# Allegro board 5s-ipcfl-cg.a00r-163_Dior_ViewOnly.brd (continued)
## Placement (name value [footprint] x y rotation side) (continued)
Q940  NX7002AK  [TX_SOT23_2D4_T01_H43]  54.74 48.76 180 bottom
Q941  NX7002AK  [TX_SOT23_2D4_T01_H43]  28.88 34.48 90 bottom
Q942  NX7002AK  [TX_SOT23_2D4_T01_H43]  33.5 34.91 90 bottom
Q4000  PJ2301  [TX_SOT23_2D4_122X55_H43]  23.34 136.15 90 top
Q4001  LMBT3904LT1G  [TX_SOT23_2D4_122X55_H44]  24.23 143.55 270 bottom
Q7201  NX7002AK  [TX_SOT23_2D4_T01_H43]  6.53 70.65 180 bottom
Q9308  NX7002AK  [TX_SOT23_2D4_T01_H43]  165.05 39.04 90 bottom
Q9309  NX7002AK  [TX_SOT23_2D4_T01_H43]  165.23 42.4 90 bottom
Q9344  LMBT3904LT1G  [TX_SOT23_2D4_122X55_H44]  163.98 24.84 0 top
Q9345  LMBT3904LT1G  [TX_SOT23_2D4_122X55_H44]  165.06 35.53 90 bottom
Q9346  LMBT3904LT1G  [TX_SOT23_2D4_122X55_H44]  166.96 38.53 270 top
Q9432  SSM6N15FU  [TX_SOIC_6P_26_87X53_COLY]  143.99 158.99 180 top
Q9433  AO3404A  [MX_SOT23_2D4_122X71]  6.68 127.62 180 bottom
Q9434  NX7002AK  [TX_SOT23_2D4_T01_H43]  30.12 59.17 270 top
Q9435  NX7002AK  [TX_SOT23_2D4_T01_H43]  29.09 51.48 180 top
Q9436  NX7002AK  [TX_SOT23_2D4_T01_H43]  31.24 31.1 90 bottom
Q9437  NX7002AK  [TX_SOT23_2D4_T01_H43]  32.43 27.8 270 bottom
Q9438  LMBT3904LT1G  [TX_SOT23_2D4_122X55_H44]  29.44 35.65 90 top
Q9534  NX7002AK  [TX_SOT23_2D4_T01_H43]  29.69 29.58 270 top
Q9535  NX7002AK  [TX_SOT23_2D4_T01_H43]  29.69 26.28 270 top
Q9537  NX7002AK  [TX_SOT23_2D4_T01_H43]  121.49 34.73 270 bottom
Q9540  NX7002AK  [TX_SOT23_2D4_T01_H43]  126.52 31.4 90 bottom
Q9541  NX7002AK  [TX_SOT23_2D4_T01_H43]  121.65 24.61 180 bottom
Q9542  NX7002AK  [TX_SOT23_2D4_T01_H43]  126.52 28.12 90 bottom
Q9543  NX7002AK  [TX_SOT23_2D4_T01_H43]  125 40.09 0 bottom
Q9544  NX7002AK  [TX_SOT23_2D4_T01_H43]  130.82 38.66 0 bottom
Q93025  AO3404A  [MX_SOT23_2D4_122X71]  154.28 169.03 180 top
Q93033  RN47A4  [MX_SOT323_S5]  133.15 169.03 0 top
Q93034  SIA432DJ-T4-GE3  [MX_SC70_6_VISHAY_T01]  110.85 38.36 180 bottom
Q93035  LMBT3904LT1G  [TX_SOT23_2D4_122X55_H44]  114.33 37.74 0 bottom
Q93036  LMBT3904LT1G  [TX_SOT23_2D4_122X55_H44]  163.98 29.46 0 top
Q93037  NX7002AK  [TX_SOT23_2D4_T01_H43]  121.54 28.11 270 bottom
Q93038  NX7002AK  [TX_SOT23_2D4_T01_H43]  121.52 31.46 270 bottom
Q93041  AO3404A  [MX_SOT23_2D4_122X71]  104.11 164.07 180 top
R1  330 OHM  [MX_R0402_SMALL_T01]  37.34 162.63 270 top
R2  330 OHM  [MX_R0402_SMALL_T01]  36.07 162.63 270 top
R3  0Ohm  [MX_R0402_SHORT_SMALL_T01]  79.57 76.51 180 top
R4  0Ohm  [MX_R0402_SHORT_SMALL_T01]  83.65 75.7 180 top
R5  0Ohm  [MX_R0402_SHORT_SMALL_T01]  82.02 75.25 180 top
R6  0Ohm  [MX_R0402_SHORT_SMALL_T01]  118.6 24 270 bottom
R19  0Ohm  [MX_R0805_SMALL_T02]  4.42 158.94 90 top
R20  0Ohm  [MX_R0805_SMALL_T02]  6.2 158.94 90 top
R21  0Ohm  [MX_R0805_SMALL_T02]  10.39 158.94 90 top
R22  0Ohm  [MX_R0805_SMALL_T02]  12.17 158.94 90 top
R23  75  [MX_R0805_SMALL_T02]  6.81 161.97 270 bottom
R36  2.2KOHM  [MX_R0402_SMALL_T01]  34.85 15.53 0 top
R37  2.2KOHM  [MX_R0402_SMALL_T01]  35.25 17.11 180 top
R38  2.2KOHM  [MX_R0402_SMALL_T01]  61.26 71.52 0 bottom
R39  2.2K  [MX_R0402_SMALL_T01]  43.14 105.34 90 bottom
R40  2.2K  [MX_R0402_SMALL_T01]  41.43 108.63 270 top
R55  390 Ohm  [MX_R0603_SMALL_T01]  2.24 26.17 180 top
R56  10KOhm  [MX_R0402_SMALL_T01]  4.8 30.34 90 top
R59  510 Ohm  [MX_R0603_SMALL_T01]  28.57 76.34 270 top
R60  10KOhm  [MX_R0402_SMALL_T01]  29.01 98.41 180 bottom
R62  4.7KOHM  [MX_R0402_SMALL_T01]  160.73 65.62 270 bottom
R70  1KOhm  [MX_R0402_SMALL_T01]  25.91 149.44 90 top
R71  20KOhm  [MX_R0402_SMALL_T01]  19.94 148.71 180 top
R79  4.7K  [MX_R0402_SMALL_T01]  48.94 140.73 180 top
R80  20KOhm  [MX_R0402_SMALL_T01]  19.94 147.74 180 top
R113  1K  [MX_R0402_SMALL_T01]  21.19 23.49 180 bottom
R123  22K  [MX_R0402_SMALL_T01]  40.19 15.01 270 top
R124  22K  [MX_R0402_SMALL_T01]  43.23 15.61 180 top
R181  0  [MX_R0402_SMALL_T01]  24.29 29.97 270 bottom
R182  0  [MX_R0402_SMALL_T01]  7.31 18.79 0 top
R203  3.3Ohm  [MX_R0402_SMALL_T01]  166.85 48.43 0 bottom
R204  3.3Ohm  [MX_R0402_SMALL_T01]  165.05 48.43 180 bottom
R205  100  [MX_R0402_SMALL_T01]  83.79 155.69 270 top
R206  0Ohm  [MX_R0402_SHORT_SMALL_T01]  82.52 155.69 270 top
R207  100  [MX_R0402_SMALL_T01]  6.7 37.33 90 top
R637  22  [MX_R0402_SMALL_T01]  32.23 87.09 180 bottom
R651  330 Ohm  [MX_R0603_SMALL_T01]  118.91 34.62 270 bottom
R658  330 Ohm  [MX_R0603_SMALL_T01]  129.73 28.11 180 bottom
R661  330 Ohm  [MX_R0603_SMALL_T01]  121.9 40.16 270 bottom
R663  1KOhm  [MX_R0402_SMALL_T01]  127.14 40.94 90 bottom
R931  1KOhm  [MX_R0402_SMALL_T01]  56.51 46.14 0 bottom
R932  330 Ohm  [MX_R0603_SMALL_T01]  57.53 49.34 180 bottom
R933  1KOhm  [MX_R0402_SMALL_T01]  33.63 32.55 90 bottom
R934  330 Ohm  [MX_R0603_SMALL_T01]  33.12 37.66 270 bottom
R2101  10K  [MX_R0402_SMALL_T01]  64.74 108.32 180 top
R2102  100K  [MX_R0402_SMALL_T01]  61.85 108.39 270 bottom
R2103  1K  [MX_R0402_SMALL_T01]  62.89 108.4 90 top
R2104  1K  [MX_R0402_SMALL_T01]  61.06 108.39 90 top
R2341  10K  [MX_R0402_SMALL_T01]  35.76 98.8 0 bottom
R2342  10K  [MX_R0402_SMALL_T01]  19.53 133.09 0 top
R2343  10K  [MX_R0402_SMALL_T01]  34.31 99.13 90 bottom
R2344  10K  [MX_R0402_SMALL_T01]  33.63 105.96 180 top
R2345  10K  [MX_R0402_SMALL_T01]  33.4 107.91 0 bottom
R2346  10K  [MX_R0402_SMALL_T01]  22.12 116.19 0 bottom
R2347  10K  [MX_R0402_SMALL_T01]  33.5 107.79 180 top
R2348  10K  [MX_R0402_SMALL_T01]  31.52 106.48 0 top
R2349  10K  [MX_R0402_SMALL_T01]  30.25 108.54 270 bottom
R2350  10K  [MX_R0402_SMALL_T01]  33.44 106.9 0 bottom
R2351  10K  [MX_R0402_SMALL_T01]  31.79 107.94 90 top
R2352  10K  [MX_R0402_SMALL_T01]  33.5 106.87 180 top
R2353  1M  [MX_R0402_SMALL_T01]  44.19 103.59 270 bottom
R2354  10K  [MX_R0402_SMALL_T01]  43.28 103.61 270 bottom
R2420  30  [MX_R0402_SMALL_T01]  50.24 103.93 0 bottom
R3106  0Ohm  [MX_R0402_SHORT_SMALL_T01]  60.63 20.94 270 bottom
R3107  0Ohm  [MX_R0402_SHORT_SMALL_T01]  39.62 58.66 180 bottom
R3108  0  [MX_R0402_SMALL_T01]  59.03 53.08 90 bottom
R3109  0  [MX_R0402_SMALL_T01]  59.14 55.06 180 top
R3110  10K  [MX_R0402_SMALL_T01]  52.91 102.45 180 bottom
R3111  0Ohm  [MX_R0402_SHORT_SMALL_T01]  27.56 88.04 180 top
R3112  0Ohm  [MX_R0402_SHORT_SMALL_T01]  53.74 101.22 180 bottom
R3113  0Ohm  [MX_R0402_SHORT_SMALL_T01]  36.5 57.6 90 bottom
R3114  0Ohm  [MX_R0402_SHORT_SMALL_T01]  37.41 57.6 90 bottom
R3115  0Ohm  [MX_R0402_SHORT_SMALL_T01]  38.68 56.87 270 bottom
R3116  0Ohm  [MX_R0402_SHORT_SMALL_T01]  39.62 56.85 270 bottom
R3117  0Ohm  [MX_R0402_SHORT_SMALL_T01]  40.92 57.77 90 bottom
R3118  0Ohm  [MX_R0402_SHORT_SMALL_T01]  41.83 57.8 90 bottom
R3119  0Ohm  [MX_R0402_SHORT_SMALL_T01]  44.78 57.47 180 bottom
R3120  0Ohm  [MX_R0402_SHORT_SMALL_T01]  44.78 56.56 180 bottom
R3121  0Ohm  [MX_R0402_SHORT_SMALL_T01]  54.89 60.42 90 bottom
R3122  0Ohm  [MX_R0402_SHORT_SMALL_T01]  53.97 60.42 90 bottom
R3123  0Ohm  [MX_R0402_SHORT_SMALL_T01]  56.26 61.23 90 bottom
R3124  0Ohm  [MX_R0402_SHORT_SMALL_T01]  57.17 61.23 90 bottom
R3125  22  [MX_R0402_SMALL_T01]  38.71 47.92 270 top
R3126  33  [MX_R0402_SMALL_T01]  38.2 108.78 90 top
R3127  22  [MX_R0402_SMALL_T01]  41.38 47.77 90 top
R3128  33  [MX_R0402_SMALL_T01]  41.86 103.72 90 bottom
R3129  0Ohm  [MX_R0402_SHORT_SMALL_T01]  46.39 47.77 90 top
R3130  0Ohm  [MX_R0402_SHORT_SMALL_T01]  47.75 44.11 180 top
R3131  0Ohm  [MX_R0402_SHORT_SMALL_T01]  47.46 47.53 90 top
R3132  33  [MX_R0402_SMALL_T01]  43.13 94.31 90 bottom
R3133  33  [MX_R0402_SMALL_T01]  32.46 99.15 0 top
R3134  33  [MX_R0402_SMALL_T01]  43.38 97.25 0 bottom
R3135  33  [MX_R0402_SMALL_T01]  32.5 97.48 0 bottom
R3136  1K  [MX_R0402_SMALL_T01]  53.39 52.03 90 bottom
R3138  1K  [MX_R0402_SMALL_T01]  20.9 106.29 180 top
R3139  0Ohm  [MX_R0402_SHORT_SMALL_T01]  50.87 55.39 0 bottom
R4000  0Ohm  [MX_R0805_SMALL_T02]  23.6 139.56 270 top
R4001  1K  [MX_R0402_SMALL_T01]  20.09 144.41 270 bottom
R4002  15KOhm  [MX_R0402_SMALL_T01]  19.82 142.79 270 bottom
R4003  200KOHM  [MX_R0402_SMALL_T01]  25.8 135.12 270 top
R4004  1KOhm  [MX_R0402_SMALL_T01]  21.06 142.79 90 bottom
R4005  1KOhm  [MX_R0402_SMALL_T01]  25.75 141.38 0 bottom
R4006  10KOhm  [MX_R0402_SMALL_T01]  26.17 133.85 0 top
R4007  0  [MX_R0402_SHORT_SMALL_T01]  21.06 144.41 90 bottom
R4008  0  [MX_R0402_SHORT_SMALL_T01]  24.74 138.17 270 bottom
R4009  10K  [MX_R0402_SMALL_T01]  15.09 138.8 90 bottom
R4010  2.49KOHM  [MX_R0402_SMALL_T01]  22.58 136.39 270 bottom
R4011  0Ohm  [MX_R0402_SHORT_SMALL_T01]  15.06 140.42 270 bottom
R4814  200  [MX_R0805_SMALL_T02]  161.4 25.4 270 top
R4815  200  [MX_R0805_SMALL_T02]  168 35.81 90 bottom
R4816  200  [MX_R0805_SMALL_T02]  164.7 34.46 90 top
R4817  200  [MX_R0805_SMALL_T02]  167.5 35.94 180 top
R4818  200  [MX_R0805_SMALL_T02]  168 41.65 270 top
R4820  200  [MX_R0805_SMALL_T02]  168 39.11 90 bottom
R4821  200  [MX_R0805_SMALL_T02]  167.99 44.44 90 top
R6501  10K  [MX_R0402_SMALL_T01]  30.68 33.14 90 top
R6502  1K  [MX_R0402_SMALL_T01]  31.88 30.7 0 top
R7202  8.2K  [MX_R0402_SMALL_T01]  7.34 67.05 270 top
R7203  0 Ohm  [MX_R0402_SMALL_T01]  8.23 71.74 90 top
R7204  33  [MX_R0402_SMALL_T01]  17.19 69.79 0 bottom
R7205  33  [MX_R0402_SMALL_T01]  13.77 71.82 90 bottom
R7206  33  [MX_R0402_SMALL_T01]  11.86 71.82 90 bottom
R7209  8.2K  [MX_R0402_SMALL_T01]  9.17 71.74 90 top
R7210  10K  [MX_R0402_SMALL_T01]  12.8 71.49 270 top
R7211  10K  [MX_R0402_SMALL_T01]  17.17 71.06 270 bottom
R7212  0  [MX_R0402_SMALL_T01]  9.4 67.58 0 bottom
R7213  0  [MX_R0402_SMALL_T01]  17.7 65.58 180 bottom
R7215  0  [MX_R0402_SMALL_T01]  14.2 73.14 0 top
R7216  0  [MX_R0402_SMALL_T01]  14.71 71.47 90 top
R7217  0  [MX_R0402_SMALL_T01]  7.31 64.48 270 bottom
R7218  0  [MX_R0402_SMALL_T01]  6.37 64.48 270 bottom
R7219  0Ohm  [MX_R0402_SHORT_SMALL_T01]  6.93 70.68 180 top
R8828  4.7K  [MX_R0402_SMALL_T01]  161.4 23.11 270 top
R8829  4.7K  [MX_R0402_SMALL_T01]  164.69 32.12 180 top
R60757  0Ohm  [MX_R0805_SMALL_T02]  67.79 90.03 180 top
R60758  0Ohm  [MX_R0805_SMALL_T02]  67.77 86.48 180 top
R60759  0Ohm  [MX_R0805_SMALL_T02]  69.24 91.81 180 top
R60760  0Ohm  [MX_R0805_SMALL_T02]  67.77 88.25 180 top
R60761  0Ohm  [MX_R0805_SHORT_SMALL_T02]  67.92 84.7 180 top
R69683  330 Ohm  [MX_R0603_SMALL_T01]  129.35 31.54 270 bottom
R69684  330 Ohm  [MX_R0603_SMALL_T01]  125.16 24.81 180 bottom
R69692  200K  [MX_R0402_SMALL_T01]  9.2 23.62 0 top
R69693  0Ohm  [MX_R0402_SHORT_SMALL_T01]  7.6 21.69 0 top
R69695  1K  [MX_R0402_SMALL_T01]  11.17 13.27 0 top
R69867  160OHM  [MX_R0402_SMALL_T01]  6.75 118.01 180 bottom
R70259  4.7K  [MX_R0402_SMALL_T01]  63.85 149.34 180 bottom
R70261  4.7K  [MX_R0402_SMALL_T01]  40.38 170.17 270 top
R70262  100K  [MX_R0402_SMALL_T01]  9.2 22.6 0 top
R70263  100K  [MX_R0402_SMALL_T01]  7.6 23.62 180 top
R70264  100K  [MX_R0402_SMALL_T01]  7.6 22.6 180 top
R70273  100K  [MX_R0402_SMALL_T01]  16.64 18.25 0 bottom
R70274  1KOhm  [MX_R0402_SMALL_T01]  9.45 15.83 90 top
R70275  1KOhm  [MX_R0402_SMALL_T01]  21.95 14.98 0 top
R70279  2.7K  [MX_R0402_SMALL_T01]  5.88 87.57 90 top
R70280  2.7K  [MX_R0402_SMALL_T01]  7.11 87.54 90 top
R70290  8.2KOHM  [MX_R0402_SMALL_T01]  28.9 55.67 180 top
R70291  8.2KOHM  [MX_R0402_SMALL_T01]  29.21 54.4 270 top
R70292  8.2KOHM  [MX_R0402_SMALL_T01]  32.59 28.95 270 top
R70293  8.2KOHM  [MX_R0402_SMALL_T01]  29.46 28.39 270 bottom
R70294  22K  [MX_R0402_SMALL_T01]  10.75 97.26 180 top
R70295  4.7K  [MX_R0402_SMALL_T01]  31.6 33.14 90 top
R70296  0Ohm  [MX_R0402_SHORT_SMALL_T01]  32.89 34.61 180 top
R70297  10K  [MX_R0402_SMALL_T01]  27.91 33.14 90 top
R70298  0Ohm  [MX_R0402_SHORT_SMALL_T01]  28.83 33.14 270 top
R70299  10K  [MX_R0402_SMALL_T01]  31.09 24.12 180 top
R70300  6.04KOhm  [TX_R0402]  84.05 74.03 270 top
R70301  4.7K  [MX_R0402_SMALL_T01]  93.84 28.11 270 bottom
R93098  0Ohm  [MX_R0402_SHORT_SMALL_T01]  134.29 165.98 90 top
R93100  22K  [MX_R0402_SMALL_T01]  157.2 169.53 0 top
R93101  10KOhm  [MX_R0402_SMALL_T01]  135.1 170.17 270 top
R93102  0Ohm  [MX_R0402_SHORT_SMALL_T01]  132.94 165.47 0 top
R93103  0  [MX_R0402_SMALL_T01]  110.31 40.51 180 bottom
R93104  100KOHM  [MX_R0402_SMALL_T01]  113.5 40.36 0 bottom
R93105  15KOhm  [MX_R0402_SMALL_T01]  114.34 41.32 180 bottom
R93106  10KOhm  [MX_R0402_SMALL_T01]  117.99 37.87 180 bottom
R93107  10KOhm  [MX_R0402_SMALL_T01]  116.57 36.27 90 bottom
R93108  8.2KOHM  [MX_R0402_SMALL_T01]  116.57 38.35 90 bottom
R93109  33 OHM  [MX_R0402_SMALL_T01]  108.95 43.25 180 bottom
R93110  1.5K  [MX_R0402_SMALL_T01]  108.39 41.32 0 bottom
R93111  200  [MX_R0805_SMALL_T02]  161.4 30.1 90 top
R93112  4.7K  [MX_R0402_SMALL_T01]  161.4 27.81 270 top
R93115  16KOHM  [MX_R0402_SMALL_T01]  38.48 109.03 0 bottom
R93116  59KOHM  [MX_R0402_SMALL_T01]  37.77 112.92 90 bottom
R93117  3KOHM  [MX_R0402_SMALL_T01]  38.68 112.92 270 bottom
R93118  2M  [MX_R0402_SMALL_T01]  19.07 95.42 90 top
R93119  150  [MX_R0402_SMALL_T01]  84.48 120.89 0 bottom
R93121  330 Ohm  [MX_R0603_SMALL_T01]  118.42 28.11 0 bottom
R93122  330 Ohm  [MX_R0603_SMALL_T01]  118.95 31.55 270 bottom
R93166  0  [MX_R0402_SMALL_T01]  73.51 64.25 90 bottom
R99508  1M  [MX_R0402_SMALL_T01]  123.04 157.6 270 top
R99511  0  [MX_R0402_SMALL_T01]  9.17 65.58 0 bottom
R99512  10K  [MX_R0402_SMALL_T01]  14.17 73.4 180 bottom
R99513  0  [MX_R0402_SMALL_T01]  14.42 63.57 0 bottom
R99514  10K  [MX_R0402_SMALL_T01]  13.79 71.87 270 top
R99515  0Ohm  [MX_R0603_SMALL_T01]  30.45 67.55 180 top
R99516  150  [MX_R0402_SMALL_T01]  33.4 108.7 180 top
R99517  4.7K  [MX_R0402_SMALL_T01]  76.73 151.91 0 bottom
R99518  0  [MX_R0402_SMALL_T01]  52.4 138.93 270 top
R99519  4.7K  [MX_R0402_SMALL_T01]  50.8 83.45 180 bottom
R99521  100  [MX_R0402_SMALL_T01]  78.21 64.38 270 top
R99522  100  [MX_R0402_SMALL_T01]  74.23 64.11 180 top
R99523  4.7K  [MX_R0402_SMALL_T01]  72.03 19.88 0 top
R99527  0Ohm  [TX_R0603_SHORT]  37.01 122.54 0 bottom
R99528  60.4 OHM  [MX_R0402_SMALL_T01]  82.65 75.43 45 bottom
R99529  2.74KOHM  [TX_R0402]  32.13 31.61 0 top
R99530  1.5K  [MX_R0402_SMALL_T01]  108.39 42.26 0 bottom
R99531  0Ohm  [MX_R0402_SHORT_SMALL_T01]  106.07 39.13 90 bottom
R99532  0  [MX_R0402_SMALL_T01]  106.07 40.78 270 bottom
R99535  1K  [MX_R0402_SMALL_T01]  43 133.47 90 bottom
R99536  75KOHM  [MX_R0402_SMALL_T01]  41.58 133.47 90 bottom
RF3  10PF/50V  [MX_C0402_SMALL_T01]  56.83 51.78 0 top
RN11  0Ohm  [MX_2R4P0603_SHORT]  30.92 55.76 0 top
RN43  0OHM  [TX_2R4P0201_35X28_SHORT]  63.47 20.28 180 top
RN44  0OHM  [TX_2R4P0201_35X28_SHORT]  65.12 20.18 180 top
RN80  0  [MX_2R4P0402]  40.72 153.73 0 top
RN86  0  [MX_2R4P0402]  42.25 153.73 0 top
RN89  0  [MX_2R4P0402]  60.8 161.55 0 top
RN90  0ohm  [TX_2R4P0201_35X28]  70.04 150.84 0 top
RN91  0ohm  [TX_2R4P0201_35X28]  71.9 150.9 0 top
RN93  0ohm  [TX_2R4P0201_35X28]  69.77 148.78 180 bottom
RN94  0ohm  [TX_2R4P0201_35X28]  71.66 148.21 180 bottom
RN95  0  [MX_2R4P0402]  62.34 161.57 0 top
RN107  0ohm  [TX_2R4P0201_35X28]  78.08 20.31 180 top
RN108  0ohm  [TX_2R4P0201_35X28]  79.86 20.31 180 top
RN109  0  [MX_2R4P0402]  69.45 18.54 180 top
RN125  0Ohm  [MX_2R4P0603_SHORT]  7.88 126.39 0 top
RN126  0Ohm  [MX_2R4P0603_SHORT]  10.12 127 0 top
RN127  0Ohm  [MX_2R4P0603_SHORT]  12.35 127 0 top
RN128  0Ohm  [MX_2R4P0603_SHORT]  14.61 127 0 top
RN133  470 OHM  [MX_4R8P0603]  140.69 159.88 180 top
RN134  470 OHM  [MX_4R8P0603]  133.51 160.52 180 top
RN149  0  [MX_2R4P0402]  67.8 18.55 180 top
RO1  6.2KOHM  [MX_R0402_SMALL_T01]  6.7 115.14 0 bottom
RO2  4.99KOhm  [MX_R0402_SMALL_T01]  6.7 116.05 180 bottom
S1C80  100PF/50V  [MX_C0402_SMALL_T01]  56.82 48.43 180 top
S1C81  180PF/50V  [MX_C0402_SMALL_T01]  56.78 45.57 0 top
SC1  0.1UF/16V  [MX_C0402_SMALL_T01]  78.01 22.72 270 top
SC2  0.1UF/16V  [MX_C0402_SMALL_T01]  78.93 22.72 270 top
SC7  0.1UF/16V  [MX_C0402_SMALL_T01]  72.59 148.44 90 top
SC8  0.1UF/16V  [MX_C0402_SMALL_T01]  71.68 148.44 90 top
SC12  47PF/50V  [MX_C0402_SMALL_T01]  48.11 108.59 90 bottom
SC13  10PF/50V  [MX_C0402_SMALL_T01]  33.45 105.07 180 top
SC14  10PF/50V  [MX_C0402_SMALL_T01]  32.26 104.08 180 top
SC15  10PF/50V  [MX_C0402_SMALL_T01]  32.33 100.47 0 top
SC16  10PF/50V  [MX_C0402_SMALL_T01]  33.3 101.41 180 top
SC17  1UF/6.3V  [MX_C0402_SMALL_T01]  30.71 92.04 270 top
SC18  1UF/6.3V  [MX_C0402_SMALL_T01]  30.71 93.67 90 top
SC19  100PF/50V  [MX_C0402_SMALL_T01]  35.47 93.67 180 bottom
SC20  100PF/50V  [MX_C0402_SMALL_T01]  35.36 92.55 180 bottom
SC21  100PF/50V  [MX_C0402_SMALL_T01]  34.25 90.84 180 top
SC22  100PF/50V  [MX_C0402_SMALL_T01]  34.25 89.91 180 top
SC23  0.1UF/16V  [MX_C0402_SMALL_T01]  21.91 91.18 0 bottom
SC24  680PF/50V  [MX_C0402_SMALL_T01]  49.93 105.2 270 bottom
SC25  0.1UF/6.3V  [TX_C0201]  31.47 65.14 180 top
SC26  1000PF/50V  [MX_C0402_SMALL_T01]  38.05 64.48 0 top
SC27  1000PF/50V  [MX_C0402_SMALL_T01]  39.52 79.52 90 bottom
SC28  0.1UF/16V  [MX_C0402_SMALL_T01]  32.66 81.06 0 bottom
SC29  15PF/50V  [MX_C0402_SMALL_T01]  40.46 76.55 90 top
SC30  15PF/50V  [MX_C0402_SMALL_T01]  39.42 75.02 270 top
SC31  12PF/50V  [MX_C0402_SMALL_T01]  53.93 108.93 0 top
SC32  12PF/50V  [MX_C0402_SMALL_T01]  52.05 107.99 180 top
SC52  15PF/50V  [MX_C0402_SMALL_T01]  26.02 94.96 180 bottom
SC53  100uF/16V  [MX_CE_98_BD268_H315_D33_LFH]  68.82 23.62 0 top
SC72  10PF/50V  [MX_C0402_SMALL_T01]  32.88 88.36 270 bottom
SC73  10PF/50V  [MX_C0402_SMALL_T01]  38.75 86.27 180 bottom
SC83  0.1UF/16V  [MX_C0402_SMALL_T01]  32.1 63.87 90 top
SC84  0.1UF/16V  [MX_C0402_SMALL_T01]  40.08 109.01 270 top
SC85  0.1UF/16V  [MX_C0402_SMALL_T01]  47.67 110.91 270 top
SC86  0.1UF/16V  [MX_C0402_SMALL_T01]  49.34 109.72 180 top
SC87  10PF/50V  [MX_C0402_SMALL_T01]  19.45 32.5 270 top
SC88  0.1UF/16V  [MX_C0402_SMALL_T01]  62.91 137.27 90 top
SC89  0.1UF/16V  [MX_C0402_SMALL_T01]  61.97 137.28 90 top
SC144  0.1UF/16V  [MX_C0402_SMALL_T01]  63.12 22.49 270 top
SC145  0.1UF/16V  [MX_C0402_SMALL_T01]  64.03 22.49 270 top
SC146  0.1UF/6.3V  [TX_C0201]  53.64 86.36 90 bottom
SCB27  0.1UF/16V  [MX_C0402_SMALL_T01]  34.01 75.4 180 top
SCB68  10PF/50V  [MX_C0402_SMALL_T01]  27.68 101.77 0 bottom
SCB69  47PF/50V  [MX_C0402_SMALL_T01]  26.72 104.21 180 bottom
SCB70  10PF/50V  [MX_C0402_SMALL_T01]  27.1 100.32 180 bottom
SCB75  10PF/50V  [MX_C0402_SMALL_T01]  5.7 95.32 180 bottom
SCB119  10PF/50V  [MX_C0402_SMALL_T01]  26.69 102.96 180 bottom
SCB121  10PF/50V  [MX_C0402_SMALL_T01]  31.85 85.83 90 bottom
SCB122  0.1UF/16V  [MX_C0402_SMALL_T01]  48.28 86.8 90 bottom
SCB123  0.1UF/16V  [MX_C0402_SMALL_T01]  49.7 86.96 90 bottom
SCB124  0.1UF/16V  [MX_C0402_SMALL_T01]  45.24 91.63 0 bottom
SCB125  0.1UF/16V  [MX_C0402_SMALL_T01]  30.33 70.86 180 top
SCB126  10PF/50V  [MX_C0402_SMALL_T01]  154.1 162.65 270 top
SCB127  22UF/6.3V  [MX_C0805_SMALL_T02]  29.23 69.43 180 top
SR9  10K  [MX_R0402_SMALL_T01]  60.78 79.75 0 bottom
SR16  10K  [MX_R0402_SMALL_T01]  30.25 80.41 0 top
SR17  8.2KOHM  [MX_R0402_SMALL_T01]  43.13 88.71 0 bottom
SR18  10K  [MX_R0402_SMALL_T01]  46.42 74.49 90 top
SR19  0Ohm  [MX_R0402_SHORT_SMALL_T01]  31.96 88.36 90 bottom
SR20  8.2KOHM  [MX_R0402_SMALL_T01]  64.72 70.37 180 top
SR21  10K  [MX_R0402_SMALL_T01]  63.79 76.38 180 bottom
SR22  10K  [MX_R0402_SMALL_T01]  65.66 74.31 180 top
SR23  10K  [MX_R0402_SMALL_T01]  58.42 80.74 270 bottom
SR24  22  [MX_R0402_SMALL_T01]  40 86.73 90 bottom
SR25  10K  [MX_R0402_SMALL_T01]  37.34 87.15 270 bottom
SR27  5.1OHM  [TX_R0402]  47.75 81.85 90 bottom
SR28  5.1OHM  [TX_R0402]  43.69 81.96 180 bottom
SR29  5.1OHM  [TX_R0402]  43.15 78.88 90 bottom
SR30  0Ohm  [MX_R0402_SHORT_SMALL_T01]  41.35 80.38 90 bottom
SR34  10K  [MX_R0402_SMALL_T01]  41.51 88.65 0 bottom
SR35  0  [MX_R0402_SMALL_T01]  45.44 73.95 270 top
SR39  10K  [MX_R0402_SMALL_T01]  51.38 72.63 180 bottom
SR40  10K  [MX_R0402_SMALL_T01]  52.7 72.23 270 bottom
SR41  10K  [MX_R0402_SMALL_T01]  49.25 145.66 0 top
SR44  8.2K  [MX_R0402_SMALL_T01]  31.66 81.35 180 top
SR46  10K  [MX_R0402_SMALL_T01]  61.26 72.43 180 bottom
SR50  10K  [MX_R0402_SMALL_T01]  60.81 82.03 90 bottom
SR52  10K  [MX_R0402_SMALL_T01]  56.11 78.09 270 bottom
SR53  10K  [MX_R0402_SMALL_T01]  56.74 71.83 270 bottom
SR57  10K  [MX_R0402_SMALL_T01]  59.61 71.52 0 bottom
SR70  10K  [MX_R0402_SMALL_T01]  51.16 78.58 90 bottom
SR71  10K  [MX_R0402_SMALL_T01]  51.6 81.73 0 bottom
SR72  10K  [MX_R0402_SMALL_T01]  56.92 82.03 180 bottom
SR73  10K  [MX_R0402_SMALL_T01]  55.55 84.85 180 bottom
SR75  47KOHM  [MX_R0402_SMALL_T01]  40.31 108.68 270 bottom
SR78  0Ohm  [MX_R0402_SMALL_T01]  59.13 49.93 90 bottom
SR79  0Ohm  [MX_R0402_SMALL_T01]  27.96 30.85 90 bottom
SR84  10K  [MX_R0402_SMALL_T01]  52.53 82.67 0 bottom
SR85  10K  [MX_R0402_SMALL_T01]  55.48 86.11 90 bottom
SR86  10K  [MX_R0402_SMALL_T01]  53.95 79.21 180 bottom
SR87  30  [MX_R0402_SMALL_T01]  49.25 108.45 90 top
SR88  10K  [MX_R0402_SMALL_T01]  54.18 80.9 270 bottom
SR93  1K  [MX_R0402_SMALL_T01]  49.04 108.59 90 bottom
SR103  10K  [MX_R0402_SMALL_T01]  55.14 81.85 270 bottom
SR104  10K  [MX_R0402_SMALL_T01]  65.63 77.21 180 top
SR105  10K  [MX_R0402_SMALL_T01]  66.01 79.87 90 top
SR108  10K  [MX_R0402_SMALL_T01]  50.7 77.23 180 bottom
SR110  10K  [MX_R0402_SMALL_T01]  29.88 84.27 0 top
SR111  10K  [MX_R0402_SMALL_T01]  29.88 83.35 0 top
SR112  10K  [MX_R0402_SMALL_T01]  51.95 85.64 270 bottom
SR115  1K  [MX_R0402_SMALL_T01]  49.93 78.58 90 bottom
SR116  10K  [MX_R0402_SMALL_T01]  67.32 145.25 270 bottom
SR117  10K  [MX_R0402_SMALL_T01]  60.78 70.55 180 bottom
SR118  10K  [MX_R0402_SMALL_T01]  53.22 85.16 0 bottom
SR120  0 Ohm  [MX_R0402_SMALL_T01]  33.64 85.32 0 top
SR121  2.2K  [MX_R0402_SMALL_T01]  32.78 83.95 0 top
SR122  1K  [MX_R0402_SMALL_T01]  32.26 85.21 270 top
SR123  1K  [MX_R0402_SMALL_T01]  47.6 145.66 0 top
SR124  33  [MX_R0402_SMALL_T01]  30.17 101.74 0 top
SR125  33  [MX_R0402_SMALL_T01]  30.53 100.42 0 top
SR132  33  [MX_R0402_SMALL_T01]  31.41 103.17 0 top
SR133  33  [MX_R0402_SMALL_T01]  31.6 104.99 0 top
SR134  1KOhm  [MX_R0402_SMALL_T01]  27.89 66.33 270 bottom
SR135  10KOhm  [MX_R0402_SMALL_T01]  21.72 65.24 90 bottom
SR136  30OHM  [MX_R0402_SMALL_T01]  43.47 108.74 270 top
SR137  30OHM  [MX_R0402_SMALL_T01]  42.53 108.74 270 top
SR151  51  [MX_R0402_SMALL_T01]  8.26 45.67 180 bottom
SR153  51  [MX_R0402_SMALL_T01]  43.92 110.91 270 top
SR154  0 Ohm  [MX_R0402_SMALL_T01]  19.82 45.31 90 bottom
SR155  0 Ohm  [MX_R0402_SMALL_T01]  18.86 45.31 90 bottom
SR158  51  [MX_R0402_SMALL_T01]  45.84 110.95 270 top
SR160  1K  [MX_R0402_SMALL_T01]  29.78 92.36 90 top
SR161  1K  [MX_R0402_SMALL_T01]  29.79 94.02 270 top
SR162  1KOhm  [MX_R0402_SMALL_T01]  11.87 45.31 270 bottom
SR163  499  [MX_R0402_SMALL_T01]  33.25 93.61 0 bottom
SR164  499  [MX_R0402_SMALL_T01]  33.29 92.7 0 bottom
SR165  0 Ohm  [MX_R0402_SMALL_T01]  11.18 59.58 180 bottom
SR166  1KOhm  [MX_R0402_SMALL_T01]  9.53 45.31 270 bottom
SR167  0 Ohm  [MX_R0402_SMALL_T01]  13.4 57.88 90 bottom
SR168  1K  [MX_R0402_SMALL_T01]  34.2 90.49 0 bottom
SR169  1K  [MX_R0402_SMALL_T01]  34.2 89.58 0 bottom
SR170  4.7K  [MX_R0402_SMALL_T01]  33.2 94.88 0 top
SR171  4.7K  [MX_R0402_SMALL_T01]  33.06 93 0 top
SR173  51  [MX_R0402_SMALL_T01]  44.85 110.91 270 top
SR184  20K  [MX_R0402_SMALL_T01]  33.35 93.94 0 top
SR185  20K  [MX_R0402_SMALL_T01]  35.33 92.73 270 top
SR211  4.7K  [MX_R0402_SMALL_T01]  30.22 90.29 270 top
SR212  100K  [MX_R0402_SMALL_T01]  32.61 77.89 270 bottom
SR213  100K  [MX_R0402_SMALL_T01]  75.92 25.52 0 top
SR214  100K  [MX_R0402_SMALL_T01]  27.28 47.39 180 bottom
SR215  100K  [MX_R0402_SMALL_T01]  27.41 42.79 180 bottom
SR216  100K  [MX_R0402_SMALL_T01]  24.61 59.17 0 bottom
SR217  100K  [MX_R0402_SMALL_T01]  4.55 57.9 270 top
SR218  100K  [MX_R0402_SMALL_T01]  27.41 53.71 270 bottom
SR219  100K  [MX_R0402_SMALL_T01]  30.91 94.33 270 bottom
SR220  100K  [MX_R0402_SMALL_T01]  21.4 32.5 270 top
SR221  100K  [MX_R0402_SMALL_T01]  18.57 54.19 90 top
SR222  100K  [MX_R0402_SMALL_T01]  47.6 69.5 0 top
SR226  49.9K  [MX_R0402_SMALL_T01]  40.77 95.47 270 bottom
SR228  4.7K  [MX_R0402_SMALL_T01]  38.89 95.62 270 bottom
SR229  20K  [MX_R0402_SMALL_T01]  39.31 93.77 180 bottom
SR230  1K  [MX_R0402_SMALL_T01]  31.47 90.19 90 top
SR237  10KOhm  [MX_R0402_SMALL_T01]  64.72 67.76 180 bottom
SR251  10K  [MX_R0402_SMALL_T01]  33.53 80.05 0 top
SR252  10K  [MX_R0402_SMALL_T01]  32.58 78.17 0 top
SR253  10K  [MX_R0402_SMALL_T01]  32.69 79.11 0 top
SR254  4.7K  [MX_R0402_SMALL_T01]  32.69 77.21 0 top
SR255  1K  [MX_R0402_SMALL_T01]  38.05 66.54 180 top
SR256  10K  [MX_R0402_SMALL_T01]  21.87 73.83 0 bottom
SR257  1M  [MX_R0402_SMALL_T01]  31.47 66.16 0 top
SR258  4.7K  [MX_R0402_SMALL_T01]  37.18 94.35 0 bottom
SR259  1K  [MX_R0402_SMALL_T01]  50.61 108.18 180 bottom
SR262  0Ohm  [MX_R0402_SHORT_SMALL_T01]  38.05 65.45 0 top
SR264  2.2K  [MX_R0402_SMALL_T01]  40.05 110.35 180 top
SR265  470  [MX_R0402_SMALL_T01]  134.21 45.24 270 bottom
SR266  619  [MX_R0402_SMALL_T01]  50.24 106.85 90 bottom
SR267  2.2K  [MX_R0402_SMALL_T01]  66.39 119.88 0 top
SR271  0Ohm  [MX_R0402_SHORT_SMALL_T01]  29.95 95.62 0 bottom
SR272  1.5K  [MX_R0402_SMALL_T01]  39.11 83.58 0 bottom
SR274  0Ohm  [MX_R0402_SHORT_SMALL_T01]  38.3 111.19 270 top
SR275  0Ohm  [MX_R0402_SHORT_SMALL_T01]  49.38 111.75 180 top
SR277  4.7K  [MX_R0402_SMALL_T01]  54.48 78.3 180 bottom
SR280  100K  [MX_R0402_SMALL_T01]  20.65 28.54 90 top
SR286  0Ohm  [MX_R0402_SHORT_SMALL_T01]  33.78 63.36 0 top
SR288  10K  [MX_R0402_SMALL_T01]  32.66 81.98 0 bottom
SR289  100K  [MX_R0402_SMALL_T01]  35.43 63.49 0 top
SR290  10K  [MX_R0402_SMALL_T01]  40.44 79.52 90 bottom
SR291  10K  [MX_R0402_SMALL_T01]  38.05 63.52 0 top
SR292  100K  [MX_R0402_SMALL_T01]  39.15 109.01 270 top
SR297  20K  [MX_R0402_SMALL_T01]  50.08 81.12 270 bottom
SR298  20K  [MX_R0402_SMALL_T01]  55.95 79.72 90 bottom
SR315  60.4 OHM  [MX_R0402_SMALL_T01]  54.91 105.65 90 bottom
SR316  100  [MX_R0402_SMALL_T01]  66.19 98.87 0 top
SR320  10MOhm  [MX_R0402_SMALL_T01]  41.38 75.71 90 top
SR321  200K  [MX_R0402_SMALL_T01]  53.67 107.99 180 top
SR322  113  [MX_R0402_SMALL_T01]  61.97 108.39 90 top
SR338  0  [MX_R0402_SMALL_T01]  49.07 93.13 270 bottom
SR342  10K  [MX_R0402_SMALL_T01]  57.68 71.95 270 bottom
SR343  10K  [MX_R0402_SMALL_T01]  59.99 69.23 270 bottom
SR344  10K  [MX_R0402_SMALL_T01]  52.75 74.89 90 bottom
SR345  10K  [MX_R0402_SMALL_T01]  51.81 74.89 90 bottom
SR346  10K  [MX_R0402_SMALL_T01]  57.53 75.83 270 bottom
SR400  10KOhm  [MX_R0402_SMALL_T01]  64.44 72.99 0 bottom
SR401  10KOhm  [MX_R0402_SMALL_T01]  62.18 74.92 270 bottom
SR402  10KOhm  [MX_R0402_SMALL_T01]  48.13 76.59 270 bottom
SR403  10KOhm  [MX_R0402_SMALL_T01]  49.07 76.24 270 bottom
SR404  10KOhm  [MX_R0402_SMALL_T01]  64.64 69.46 180 top
SR406  10KOhm  [MX_R0402_SMALL_T01]  45.9 87.52 270 bottom
SR407  10KOhm  [MX_R0402_SMALL_T01]  60.93 69.23 270 bottom
SR410  8.2K  [MX_R0402_SMALL_T01]  32.5 96.54 180 bottom
SR411  10K  [MX_R0402_SMALL_T01]  37.44 99.28 90 bottom
SR416  10KOhm  [MX_R0402_SMALL_T01]  29.74 65.65 270 top
SR420  10KOhm  [MX_R0402_SMALL_T01]  64.72 68.72 0 bottom
SR546  0 Ohm  [MX_R0402_SMALL_T01]  55.8 68.14 180 bottom
SR547  0 Ohm  [MX_R0402_SMALL_T01]  54.13 74.36 0 bottom
SR548  0 Ohm  [MX_R0402_SMALL_T01]  56.41 73.8 0 bottom
SR549  0 Ohm  [MX_R0402_SMALL_T01]  57.83 70.27 270 bottom
SR552  1K  [MX_R0402_SMALL_T01]  50.6 109.95 90 top
SR624  0 Ohm  [MX_R0402_SMALL_T01]  14 45.31 90 bottom
SR625  0 Ohm  [MX_R0402_SMALL_T01]  13.06 45.31 90 bottom
SR669  10KOhm  [MX_R0402_SMALL_T01]  57.68 69 0 bottom
SR672  10KOhm  [MX_R0402_SMALL_T01]  28.83 88.64 270 top
SR673  10KOhm  [MX_R0402_SMALL_T01]  36.33 88.83 0 bottom
SR674  10KOhm  [MX_R0402_SMALL_T01]  31.96 87.81 0 top
SR698  10KOhm  [MX_R0402_SMALL_T01]  33.4 109.64 0 top
SR699  10KOhm  [MX_R0402_SMALL_T01]  28.93 113.27 90 top
SR700  10KOhm  [MX_R0402_SMALL_T01]  29.21 107.11 0 top
SR701  10KOhm  [MX_R0402_SMALL_T01]  29.36 106.2 0 top
SR702  20KOhm  [MX_R0402_SMALL_T01]  33.42 110.66 180 top
SR703  20KOhm  [MX_R0402_SMALL_T01]  29.72 105.28 0 top
SR750  0 Ohm  [MX_R0402_SMALL_T01]  20.3 57.88 270 bottom
SR751  0 Ohm  [MX_R0402_SMALL_T01]  19.36 57.88 270 bottom
SR752  0 Ohm  [MX_R0402_SMALL_T01]  18.35 57.88 270 bottom
SR753  0 Ohm  [MX_R0402_SMALL_T01]  17.33 57.88 270 bottom
SR754  0 Ohm  [MX_R0402_SMALL_T01]  16.32 57.88 270 bottom
SR755  0 Ohm  [MX_R0402_SMALL_T01]  15.3 57.88 270 bottom
SR756  0 Ohm  [MX_R0402_SMALL_T01]  14.37 58.79 270 bottom
SR758  1KOhm  [MX_R0402_SMALL_T01]  10.4 57.88 270 bottom
SR759  0 Ohm  [MX_R0402_SMALL_T01]  8.34 59.2 0 bottom
SR760  1KOhm  [MX_R0402_SMALL_T01]  5.23 59.73 90 bottom
SR763  1KOhm  [MX_R0402_SMALL_T01]  46.85 110.44 180 bottom
SR764  0 Ohm  [MX_R0402_SMALL_T01]  46.75 110.95 270 top
SR765  51  [MX_R0402_SMALL_T01]  46.35 108.68 270 top
SR766  100  [MX_R0402_SMALL_T01]  47.26 108.68 270 top
SR767  51  [MX_R0402_SMALL_T01]  7.6 57.91 270 bottom
SR768  0 Ohm  [MX_R0402_SMALL_T01]  6.65 59.55 270 bottom
SR769  51  [MX_R0402_SMALL_T01]  47.03 108.61 270 bottom
SR773  2.2KOHM  [MX_R0402_SMALL_T01]  87.11 124.91 0 bottom
SR774  2.2K  [MX_R0402_SMALL_T01]  80.64 104.84 0 bottom
SR775  0 Ohm  [MX_R0402_SMALL_T01]  6.69 57.91 270 bottom
SR776  0 Ohm  [MX_R0402_SMALL_T01]  5.78 57.92 270 bottom
SR777  1KOhm  [MX_R0402_SMALL_T01]  8.53 57.91 90 bottom
SR778  0 Ohm  [MX_R0402_SMALL_T01]  5.61 56.28 270 bottom
SR817  0  [MX_R0402_SMALL_T01]  22.15 147.67 90 top
SR818  45.3KOhm  [MX_R0402_SMALL_T01]  21.23 147.67 90 top
SR823  1KOhm  [MX_R0402_SMALL_T01]  11.34 57.88 90 bottom
SR897  10K  [MX_R0402_SMALL_T01]  44.98 87.52 270 bottom
SR909  10KOhm  [MX_R0402_SMALL_T01]  36.3 89.73 0 bottom
SR911  10KOhm  [MX_R0402_SMALL_T01]  38.02 81.65 90 bottom
SR912  10KOhm  [MX_R0402_SMALL_T01]  34.9 91.63 0 bottom
SR916  20KOhm  [MX_R0402_SMALL_T01]  6 27.14 0 top
SR3701  10K  [MX_R0402_SMALL_T01]  69.19 142.46 0 top
SR7785  33  [MX_R0402_SMALL_T01]  45.57 81.88 90 bottom
SR7787  0Ohm  [MX_R0402_SHORT_SMALL_T01]  43.76 75.68 90 top
SR7791  22  [MX_R0402_SMALL_T01]  31.7 77.89 270 bottom
SR7792  22  [MX_R0402_SMALL_T01]  35.56 82.46 180 bottom
SR7794  10K  [MX_R0402_SMALL_T01]  20.93 110.66 90 bottom
SR7795  33  [MX_R0402_SMALL_T01]  20.65 34.11 270 top
SR7796  10K  [MX_R0402_SMALL_T01]  29.31 90.26 270 top
SR7802  0  [MX_R0402_SMALL_T01]  19.82 118.56 270 top
SR7803  10KOhm  [MX_R0402_SMALL_T01]  64.44 72.05 180 bottom
SR7812  0Ohm  [MX_R0402_SHORT_SMALL_T01]  31.7 101.74 90 top
SR7813  20KOhm  [MX_R0402_SMALL_T01]  7.65 26.04 0 top
SR7814  20KOhm  [MX_R0402_SMALL_T01]  6 26.2 0 top
SR7815  0  [MX_R0402_SMALL_T01]  59.5 83.44 90 bottom
SR7816  0  [MX_R0402_SMALL_T01]  56.11 76.47 270 bottom
SR7817  0  [MX_R0402_SMALL_T01]  54.79 70.88 0 bottom
SR7829  10KOhm  [MX_R0402_SMALL_T01]  54.79 69.95 0 bottom
SR7830  10KOhm  [MX_R0402_SMALL_T01]  61.26 74.92 90 bottom
SR7831  10KOhm  [MX_R0402_SMALL_T01]  60.04 76.19 0 bottom
SR7832  10KOhm  [MX_R0402_SMALL_T01]  48.07 78.5 90 bottom
SR7833  10KOhm  [MX_R0402_SMALL_T01]  47.1 78.5 90 bottom
SR7834  10K  [MX_R0402_SMALL_T01]  51.9 73.62 0 bottom
SR7838  10K  [MX_R0402_SMALL_T01]  29.84 79.39 180 top
SR7841  10K  [MX_R0402_SMALL_T01]  35.86 97.88 0 bottom
SR7842  10K  [MX_R0402_SMALL_T01]  32.41 90.86 270 top
SR7843  10K  [MX_R0402_SMALL_T01]  39.83 95.62 270 bottom
SR7844  10K  [MX_R0402_SMALL_T01]  29.03 85.7 270 top
SR7847  4.7K  [MX_R0402_SMALL_T01]  35.86 96.97 0 bottom
SR7848  10K  [MX_R0402_SMALL_T01]  51.43 70.75 180 bottom
SR7849  10K  [MX_R0402_SMALL_T01]  65.56 78.09 180 bottom
SR7850  10KOhm  [MX_R0402_SMALL_T01]  60.73 80.74 0 bottom
SR7851  10KOhm  [MX_R0402_SMALL_T01]  50.7 84.98 90 bottom
SR7852  10KOhm  [MX_R0402_SMALL_T01]  64.44 73.93 0 bottom
SR7853  4.7K  [MX_R0402_SMALL_T01]  48.84 76.47 90 top
SR7854  1.5K  [MX_R0402_SMALL_T01]  34.3 81.64 90 bottom
SR7855  22  [MX_R0402_SMALL_T01]  32.61 79.21 180 bottom
SR7856  22  [MX_R0402_SMALL_T01]  32.61 80.13 180 bottom
SR7857  10K  [MX_R0402_SMALL_T01]  36.19 78.27 180 bottom
SR7858  0 Ohm  [MX_R0402_SMALL_T01]  54.51 86.53 90 bottom
SR7862  10K  [MX_R0402_SMALL_T01]  29.88 82.44 0 top
SR7868  10K  [MX_R0402_SMALL_T01]  31.57 82.31 180 top
SR7870  10K  [MX_R0402_SMALL_T01]  32.32 86.48 180 top
SR7871  10K  [MX_R0402_SMALL_T01]  30.71 86.63 0 top
SR7872  10K  [MX_R0402_SMALL_T01]  30.81 85.38 0 top
SR7873  10K  [MX_R0402_SMALL_T01]  34.53 88.31 270 bottom
SR7874  10K  [MX_R0402_SMALL_T01]  34.42 86.43 0 top
SR7875  10K  [MX_R0402_SMALL_T01]  34.47 87.34 0 top
SR7876  20K  [MX_R0402_SMALL_T01]  45.08 40.48 90 top
SR7877  20K  [MX_R0402_SMALL_T01]  63.93 44.92 90 bottom
SR7878  10KOhm  [MX_R0402_SMALL_T01]  37.84 79.01 180 bottom
SR7879  10K  [MX_R0402_SMALL_T01]  38.72 87.19 0 bottom
SR7880  20K  [MX_R0402_SMALL_T01]  70.46 51.55 180 top
SR7882  10K  [MX_R0402_SMALL_T01]  36.31 90.64 0 bottom
SR7883  10K  [MX_R0402_SMALL_T01]  39.5 90.35 0 bottom
SR7884  20KOhm  [MX_R0402_SMALL_T01]  4.56 26.03 90 top
SR7885  499  [MX_R0402_SMALL_T01]  54.53 49.38 180 top
SR7886  499  [MX_R0402_SMALL_T01]  54.53 48.45 180 top
SR7887  10K  [MX_R0402_SMALL_T01]  55.85 52.95 180 bottom
SR7888  0Ohm  [MX_R0402_SHORT_SMALL_T01]  36.52 91.56 180 bottom
SR7889  0Ohm  [MX_R0402_SMALL_T01]  131.08 41.84 0 bottom
SR7890  0Ohm  [MX_R0402_SHORT_SMALL_T01]  122.39 37.77 0 bottom
SR7895  10K  [MX_R0402_SMALL_T01]  39.5 89.44 0 bottom
SR7896  10K  [MX_R0402_SMALL_T01]  36.32 79.59 90 bottom
SR7897  10K  [MX_R0402_SMALL_T01]  33.27 91.79 0 bottom
SR7901  0Ohm  [MX_R0402_SHORT_SMALL_T01]  106.3 169.81 180 top
SR7902  2.2K  [MX_R0402_SMALL_T01]  104.52 169.81 0 top
SR7903  10K  [MX_R0402_SMALL_T01]  111.3 170.17 270 top
SR7904  1M  [MX_R0402_SMALL_T01]  124.31 157.98 180 top
SR7905  0Ohm  [MX_R0402_SHORT_SMALL_T01]  106.27 168.52 180 top
SR7906  2.2K  [MX_R0402_SMALL_T01]  104.49 168.52 0 top
SR7907  10K  [MX_R0402_SMALL_T01]  111.02 157.5 0 top
SR7914  200  [MX_R0402_SMALL_T01]  38.5 104.05 180 bottom
SR7915  0Ohm  [MX_R0402_SHORT_SMALL_T01]  54.54 72.17 0 bottom
SR7917  0Ohm  [MX_R0402_SHORT_SMALL_T01]  66.95 64 0 bottom
SR7919  10K  [MX_R0402_SMALL_T01]  42.67 100.17 270 bottom
SR7920  10K  [MX_R0402_SMALL_T01]  40 101.18 180 bottom
SR7921  20KOhm  [MX_R0402_SMALL_T01]  48.66 97.39 180 bottom
SR7922  1K  [MX_R0402_SMALL_T01]  35.79 65.01 0 top
SR7923  1K  [MX_R0402_SMALL_T01]  32.36 67.55 90 top
SR7924  10K  [MX_R0402_SMALL_T01]  43.92 100.07 270 bottom
SR7925  10K  [MX_R0402_SMALL_T01]  45.19 99.16 0 bottom
SR7928  10K  [MX_R0402_SMALL_T01]  45.29 103.95 90 bottom
SR7929  10K  [MX_R0402_SMALL_T01]  64.16 75.71 90 top
SR7930  10K  [MX_R0402_SMALL_T01]  65.51 75.63 90 top
SR7931  10K  [MX_R0402_SMALL_T01]  60.81 77.97 180 bottom
SR7932  75KOHM  [MX_R0402_SMALL_T01]  36.3 48.5 270 top
SR7933  60.4KOHM  [MX_R0402_SMALL_T01]  37.18 46.73 180 top
SR7934  1K  [MX_R0402_SMALL_T01]  33.25 95.87 0 top
SR7935  1K  [MX_R0402_SMALL_T01]  33.25 96.83 0 top
SR7938  10K  [MX_R0402_SMALL_T01]  43.61 91.71 0 bottom
SR7939  10KOhm  [MX_R0402_SMALL_T01]  37.95 95.62 270 bottom
SR7940  10KOhm  [MX_R0402_SMALL_T01]  28.09 86.58 90 top
SR7941  10K  [MX_R0402_SMALL_T01]  33.83 96.84 270 bottom
SR7942  10K  [MX_R0402_SMALL_T01]  16.18 100.02 90 top
SR7943  10KOhm  [MX_R0402_SMALL_T01]  32.54 98.06 0 top
SR7944  10K  [MX_R0402_SMALL_T01]  39.29 81.64 180 bottom
SR7945  10K  [MX_R0402_SMALL_T01]  42.44 87.42 270 bottom
SR7946  10K  [MX_R0402_SMALL_T01]  43.43 87.04 90 bottom
SR7947  10K  [MX_R0402_SMALL_T01]  39.29 82.55 180 bottom
SR7948  10K  [MX_R0402_SMALL_T01]  57.35 79.62 90 bottom
SR7949  10K  [MX_R0402_SMALL_T01]  57.3 77.46 90 bottom
SR7950  10K  [MX_R0402_SMALL_T01]  58.23 84.31 180 bottom
SR7951  10K  [MX_R0402_SMALL_T01]  58.57 83.02 90 bottom
SR7953  10K  [MX_R0402_SMALL_T01]  71.77 55.83 0 bottom
SR7954  75KOHM  [MX_R0402_SMALL_T01]  57.63 86.63 180 bottom
SR7955  10K  [MX_R0402_SMALL_T01]  53.55 84.18 0 bottom
SR7956  10K  [MX_R0402_SMALL_T01]  65.63 78.22 180 top
SR7966  0Ohm  [MX_R0402_SMALL_T01]  73.25 56.25 270 bottom
SR7975  100  [MX_R0402_SMALL_T01]  31.98 75.35 270 top
SR7976  100  [MX_R0402_SMALL_T01]  51.38 71.67 0 bottom
SR7977  100  [MX_R0402_SMALL_T01]  59.54 78.48 90 bottom
SR7979  100  [MX_R0402_SMALL_T01]  35.66 95.62 0 bottom
SR7981  0Ohm  [MX_R0402_SHORT_SMALL_T01]  51.64 80.81 180 bottom
SR7982  4.7K  [MX_R0402_SMALL_T01]  21.31 74.03 0 top
SR7983  20K  [MX_R0402_SMALL_T01]  21.31 75.05 0 top
SR7988  100  [MX_R0402_SMALL_T01]  34.14 65.01 0 top
SR7989  100  [MX_R0402_SMALL_T01]  29.86 96.38 180 top
SR7990  100  [MX_R0402_SMALL_T01]  59.69 20.82 90 bottom
SR7991  10K  [MX_R0402_SMALL_T01]  51.03 99.85 90 bottom
SR7993  10K  [MX_R0402_SMALL_T01]  70.46 52.57 180 top
SR7994  10K  [MX_R0402_SMALL_T01]  84.43 141.47 180 bottom
SR7995  0  [MX_R0402_SMALL_T01]  77.44 143.04 90 bottom
SR7996  20KOhm  [MX_R0402_SMALL_T01]  38.58 46.29 90 top
SR7997  20KOhm  [MX_R0402_SMALL_T01]  40.56 46.07 90 top
SR7998  1K  [MX_R0402_SMALL_T01]  70 135.27 0 top
SR7999  0  [MX_R0402_SMALL_T01]  70.69 142.1 270 top
SR8000  100  [MX_R0402_SMALL_T01]  69.19 143.58 0 top
SR8001  0  [MX_R0402_SMALL_T01]  33.12 47.21 270 top
SR8002  20K  [MX_R0402_SMALL_T01]  69.19 141.42 0 top
SSD_Q1  2N3904G-TF  [DX_TO92_102_FSBREC_LF5]  26.47 83.56 0 top
SSD_Q2  LMBT3904LT1G  [TX_SOT23_2D4_122X55_H44]  13.18 89.7 90 top
ST1  TPC26T  [MX_TPC26T_S4_68]  100.66 28.95 180 bottom
ST3  TPC26T  [MX_TPC26T_S4_68]  38.05 89.65 180 bottom
ST16  TPC26T  [MX_TPC26T_S4_68]  35 105.91 180 bottom
ST17  TPC26T  [MX_TPC26T_S4_68]  49.54 100.19 180 bottom
ST20  TPC26T  [MX_TPC26T_S4_68]  49.4 83.96 180 bottom
ST24  TPC26T  [MX_TPC26T_S4_68]  50.65 108.02 0 top
ST25  TPC26T  [MX_TPC26T_S4_68]  51.28 101.86 180 bottom
ST26  TPC26T  [MX_TPC26T_S4_68]  99.25 27.56 180 bottom
ST31  TPC26T  [MX_TPC26T_S4_68]  64.84 80.48 180 bottom
ST32  TPC26T  [MX_TPC26T_S4_68]  12.7 94.6 0 top
ST33  TPC26T  [MX_TPC26T_S4_68]  44.38 76.62 180 bottom
ST34  TPC26T  [MX_TPC26T_S4_68]  54.58 75.68 180 bottom
SW10  TACT_SWITCH_4P_2HOLD_DIPTRON  [T_TACT_SW_4P_2H_RA_LF5]  3 13.3 0 top
SW_RST1  TACT_SWITCH_4P  [MX_SW_4P_181X126]  2.96 21.71 270 top
TC1  0.22UF/10V  [MX_C0402_SMALL_T01]  7.6 118.34 270 top
TC2  0.22UF/10V  [MX_C0402_SMALL_T01]  8.52 118.34 270 top
TC3  0.22UF/10V  [MX_C0402_SMALL_T01]  12.58 118.23 270 top
TC4  0.22UF/10V  [MX_C0402_SMALL_T01]  13.5 118.23 270 top
TC5  0.22UF/10V  [MX_C0402_SMALL_T01]  10.09 118.16 270 top
TC6  0.22UF/10V  [MX_C0402_SMALL_T01]  11.01 118.16 270 top
TC7  0.22UF/10V  [MX_C0402_SMALL_T01]  15.03 118.26 270 top
TC8  0.22UF/10V  [MX_C0402_SMALL_T01]  15.95 118.26 270 top
TC9  0.01UF/50V  [MX_C0402_SMALL_T01]  28.87 121.89 90 bottom
TC10  0.01UF/50V  [MX_C0402_SMALL_T01]  27.85 121.89 90 bottom
TC11  0.01UF/50V  [MX_C0402_SMALL_T01]  30.9 121.89 90 bottom
TC12  0.01UF/50V  [MX_C0402_SMALL_T01]  29.88 121.89 90 bottom
TC13  0Ohm  [MX_R0402_SHORT_SMALL_T01]  14.69 120.52 90 top
TC14  0Ohm  [MX_R0402_SHORT_SMALL_T01]  13.78 120.52 90 top
TC15  0Ohm  [MX_R0402_SHORT_SMALL_T01]  9.41 119.81 90 top
TC16  0Ohm  [MX_R0402_SHORT_SMALL_T01]  10.33 119.81 90 top
TC17  0Ohm  [MX_R0402_SHORT_SMALL_T01]  11.52 120.01 90 top
TC18  0Ohm  [MX_R0402_SHORT_SMALL_T01]  12.43 120.01 90 top
TC19  0Ohm  [MX_R0402_SHORT_SMALL_T01]  7.17 120.77 90 top
TC20  0Ohm  [MX_R0402_SHORT_SMALL_T01]  8.09 120.77 90 top
TP2601  TPC26T  [MX_TPC26T_S4_68]  48.04 85.16 180 bottom
TP2602  TPC26T  [MX_TPC26T_S4_68]  46.94 88.48 180 bottom
TP7201  TPC26T  [MX_TPC26T_S4_68]  19.51 66.11 180 bottom
TUC23  10UF/6.3V  [MX_C0603_SMALL_T01]  61.53 149.19 180 bottom
TUC24  10UF/6.3V  [MX_C0603_SMALL_T01]  40.11 167.4 180 top
TUC26  10UF/6.3V  [MX_C0603_SMALL_T01]  82.43 150.28 270 bottom
TUC27  10UF/6.3V  [MX_C0603_SMALL_T01]  96.68 25.83 270 bottom
TUC30  10UF/6.3V  [MX_C0603_SMALL_T01]  61.5 150.51 180 bottom
TUC31  10UF/6.3V  [MX_C0603_SMALL_T01]  41.81 168.7 180 top
TUC32  10UF/6.3V  [MX_C0603_SMALL_T01]  81.23 150.28 270 bottom
TUC33  10UF/6.3V  [MX_C0603_SMALL_T01]  74.14 19.73 0 top
TUC34  10UF/6.3V  [MX_C0603_SMALL_T01]  73.18 23.1 90 top
TUC35  22UF/6.3V  [TX_C0805_T02_H55]  42.26 164.78 270 top
TUC36  22UF/6.3V  [TX_C0805_T02_H55]  62 147.61 180 bottom
TUC37  22UF/6.3V  [TX_C0805_T02_H55]  79.68 150.45 270 bottom
TUC38  22UF/6.3V  [TX_C0805_T02_H55]  71.6 18.51 180 top
U1  PCH-H  [A_BGA_874P_988X949_N]  50.28 92.45 270 top
U6  ALC3234-CGT  [MX_QFN_48P_16_S240_PAD_9V]  17.89 21.84 180 top
U104  SCH5553-NU  [MX_QFP_128P_16_S630_H47]  16.11 100.56 270 bottom
U114  RTL8111HSD-CG  [MX_QFN_32P_16_S157_P_H35_8V]  19.15 138.29 180 bottom
U131  P4500SCLHLRP  [MX_A_SMB_181X157_COLAY]  4.42 158.49 180 bottom
U7201  NPCT750JAAYX  [MX_QFN_32P_20_S201_P_4V]  13.59 67.33 180 bottom
U9434  MX25L25645GM2I-08G  [MX_SOIC_8P_50_S213_NS_NP]  56.46 71.16 0 top
U9435  W25Q256JVFIQ  [TX_SOIC_16P_50_413X299_WIN]  56.44 70.81 270 top
UB1  ICS553MILFT  [MX_SOIC_8P_50_197X236]  49.82 118.72 270 bottom
UBC1  0.01UF/50V  [MX_C0402_SMALL_T01]  54.56 121.4 180 bottom
UBR1  33  [MX_R0402_SMALL_T01]  54.28 119.8 270 bottom
UBR2  33  [MX_R0402_SMALL_T01]  54.63 118.43 0 bottom
UBR3  33  [MX_R0402_SMALL_T01]  45.4 118.72 90 bottom
UU19  G524B1T11U  [MX_SOT23_S5_H57]  65.09 146.04 90 bottom
UU22  G524B1T11U  [MX_SOT23_S5_H57]  39.59 164.38 90 top
UU64  G517H1T11U  [TX_SOT23_S5_2D4_T02X01_H57]  75.72 149.67 270 bottom
UU65  G524B1T11U  [MX_SOT23_S5_H57]  99.15 24.63 90 bottom
UU66  G517H1T11U  [TX_SOT23_S5_2D4_T02X01_H57]  75.56 22.65 0 top
VD11  BAT54AW  [MX_SOT323]  146.94 159.34 0 top
X3R14  10K  [MX_R0402_SMALL_T01]  18.33 106.18 0 top
X3R20  0  [MX_R0402_SMALL_T01]  23.26 104.59 180 top
X3R21  0  [MX_R0402_SMALL_T01]  19.63 105.91 90 top
XBT1  BATT_HOLDER_2P  [MX_BATHOLDER_2P_787_LF5]  35.66 142.14 90 top
XDP1  BTOB_CON_60P  [MX_BTOB_60P_20_F_SAMT_NS_NP]  75.13 114.21 270 bottom
XDP3  BTOB_CON_60P  [MX_BTOB_60P_20_F_SAMT_NS_NP]  14.4 50.92 180 bottom
XU1  SOCKET_1151P  [MX_SOCKET1151_FOXN_3HD]  123.38 111.98 0 top
Y5  32.768KHZ  [MX_XTAL_4P_272X55]  37.87 71.88 270 top
Y18  24MHZ  [MX_XTAL_4P_126X98_HELE]  53.54 111.17 0 top
Y4000  25MHZ  [MX_XTAL_4P_126X98_HOSON_H35]  27.41 137.4 180 bottom

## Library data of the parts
AC1 AC3-AC6 AC12-AC14 AC20 AC24 AC25 AC47 AC52 AC53 AC70 AC82 AC84-AC90 AC92-AC100 AC202-AC209 C1-C12 C15-C18 C45 C49 C81-C83 C85 C86 C94 C97 C98 C200-C202 C204-C207 C248 C249 C258 C306 C316 C2715 C2726 C3101 C3102 C3907 C4000-C4023 C4301-C4310 C7201-C7210 C8301-C8316 C9478 C941488-C941492 C941623 C941625 C941629 C941631-C941636 C941643-C941649 CB171 CB4133-CB4135 CB4152 D4C1-D4C29 D4C31-D4C34 D4CB1-D4CB24 FCB1 FCB2 HC1-HC5 HC11-HC21 HC23-HC29 HCB3-HCB6 LC3-LC9 M1C43 M1C44 M1C49-M1C52 M1C66 M1C67 M1C69 M1C70 M1C73 M1C79 M1C80 M1C82 M1C83 M1C88 M1C89 M1C96 M1C97 M1C99-M1C124 MC8301-MC8305 O2C1 O2C2 O2C6-O2C8 O2CB1-O2CB8 O2CB10 O2CB11 O2CB15-O2CB17 O2CB19-O2CB21 PC1 PC4 PC5 PC17 PC19-PC76 PC78 PC79 PC81 PC92-PC97 PC99 PC102 PC104-PC130 PC134 PC135 PC760-PC762 PC802-PC804 PC808 PC812-PC816 PC998 PC999 PC6301-PC6308 PC7310 PC7601-PC7607 PC7801 PC7802 PC7899 PC8498 PC8499 PC9001-PC9003 PC9416 PC89001-PC89037 PC90001-PC90003 PC90005-PC90010 PC90012 PC90013 PC90016-PC90021 PC90100 PC93001-PC93003 PC93005-PC93010 PC93012 PC93013 PC93016-PC93021 PC97001-PC97043 PC941483-PC941485 PC941488-PC941494 PC941496 PC941497 PC941502 PC941579 PC941580 PC941582 PC941584-PC941591 PC941601-PC941605 PC941608-PC941614 PC941617-PC941620 PC941622 PC941623 PC941626 PC941663-PC941667 PC941669-PC941671 RF3 S1C80 S1C81 SC1 SC2 SC7 SC8 SC12-SC25 SC28-SC32 SC52 SC72 SC73 SC83-SC89 SC144-SC146 SCB27 SCB68-SCB70 SCB75 SCB119 SCB121-SCB127 TC1-TC12 TUC23 TUC24 TUC26 TUC27 TUC30-TUC38 = C
AMB_Q1 SSD_Q1 = NPN_TO92
APD1 APD2 = DIODE
APR5-APR10 APR46 APR115 APR117 APR119 APR120 APR124-APR128 APR130-APR137 APR142-APR144 AR14 AR15 AR17 AR19 AR22 AR23 AR29 AR38 AR40 AR41 AR43 D4R2 D4R5-D4R9 D4R14 D4R16 D4R18-D4R20 D4R22 ECR103 ECR106-ECR110 ECR135 ECR141 ECR142 ECR146 ECR156 ECR157 ECR159 ECR160 F3R1 F3R2 F3R6-F3R12 F3R22 F3R23 F3R70 F3R71 FR1 FR2 FR10 FR12 HR1 HR2 HR4-HR10 HR12 HR14 HR15 HR23 HR25 HR29 HR30 HR32-HR49 HR54 HR55 HR57 HR58 HR64 HR69 HR70 HR72 HR74 HR81-HR85 HR91 HR93 HR96 HR98 HR343 HR346 HR347 HR364-HR367 HR371-HR374 HR377-HR380 HR383-HR385 HR392 HR399 HR410 HR424 HR426 HR427 LR9-LR11 M1R10 M1R14-M1R16 M1R19-M1R26 M2R1 O2R1 O2R9 O2R10 O2R12-O2R15 O2R22 O2R24 O2R25 OR3 OR22 OR29 OR34 OR37 OR59 OR68-OR79 OR109 OR111 OR112 OR118-OR120 OR122-OR130 OR132-OR137 OR141-OR143 OR146-OR154 PR1-PR5 PR9-PR12 PR25-PR42 PR44-PR47 PR49 PR51-PR68 PR71-PR76 PR96 PR97 PR99 PR101 PR107 PR109 PR111 PR113 PR115-PR117 PR119-PR136 PR139 PR141 PR214 PR760 PR761 PR808 PR1017 PR6399 PR7401 PR7601 PR7602 PR7607-PR7609 PR7701 PR8402 PR8405 PR8901 PR89001 PR89002 PR89004-PR89008 PR89010-PR89032 PR89034-PR89050 PR89052-PR89057 PR89059-PR89073 PR89105 PR90001-PR90016 PR93001-PR93016 PR93024 PR93026 PR93028 PR93038 PR93039 PR93046 PR93051 PR93052 PR93054 PR93055 PR93060-PR93063 PR93066-PR93071 PR93083 PR93097-PR93099 PR93156 PR93158 PR93162-PR93166 R1 R2 R19-R23 R36-R40 R55 R56 R59 R60 R62 R70 R71 R79 R80 R113 R123 R124 R181 R182 R203-R205 R207 R637 R651 R658 R661 R663 R931-R934 R2101-R2104 R2341-R2354 R2420 R3108-R3110 R3125-R3128 R3132-R3136 R3138 R4000-R4006 R4009 R4010 R4814-R4818 R4820 R4821 R6501 R6502 R7202-R7206 R7209-R7213 R7215-R7218 R8828 R8829 R60757-R60760 R69683 R69684 R69692 R69695 R69867 R70259 R70261-R70264 R70273-R70275 R70279 R70280 R70290-R70295 R70297 R70299-R70301 R93100 R93101 R93103-R93112 R93115-R93119 R93121 R93122 R93166 R99508 R99511-R99519 R99521-R99523 R99528-R99530 R99532 R99535 R99536 RO1 RO2 SR9 SR16-SR18 SR20-SR25 SR27-SR29 SR34 SR35 SR39-SR41 SR44 SR46 SR50 SR52 SR53 SR57 SR70-SR73 SR75 SR78 SR79 SR84-SR88 SR93 SR103-SR105 SR108 SR110-SR112 SR115-SR118 SR120-SR125 SR132-SR137 SR151 SR153-SR155 SR158 SR160-SR171 SR173 SR184 SR185 SR211-SR222 SR226 SR228-SR230 SR237 SR251-SR259 SR264-SR267 SR272 SR277 SR280 SR288-SR292 SR297 SR298 SR315 SR316 SR320-SR322 SR338 SR342-SR346 SR400-SR404 SR406 SR407 SR410 SR411 SR416 SR420 SR546-SR549 SR552 SR624 SR625 SR669 SR672-SR674 SR698-SR703 SR750-SR756 SR758-SR760 SR763-SR769 SR773-SR778 SR817 SR818 SR823 SR897 SR909 SR911 SR912 SR916 SR3701 SR7785 SR7791 SR7792 SR7794-SR7796 SR7802 SR7803 SR7813-SR7817 SR7829-SR7834 SR7838 SR7841-SR7844 SR7847-SR7858 SR7862 SR7868 SR7870-SR7880 SR7882-SR7887 SR7889 SR7895-SR7897 SR7902-SR7904 SR7906 SR7907 SR7914 SR7919-SR7925 SR7928-SR7935 SR7938-SR7951 SR7953-SR7956 SR7966 SR7975-SR7977 SR7979 SR7982 SR7983 SR7988-SR7991 SR7993-SR8002 UBR1-UBR3 X3R14 X3R20 X3R21 = R
APR17-APR19 APR29-APR31 APR47 APR75 APR112 APR116 APR121-APR123 APR129 AR36 D4R10-D4R12 D4R17 D4R21 D4R23 ECR67 ECR73-ECR77 ECR96 ECR104 ECR129-ECR132 ECR136-ECR139 ECR143-ECR145 ECR147-ECR149 ECR154 ECR155 F3R20 F3R21 F3R24-F3R29 HR3 HR24 HR59 HR61 HR63 HR66 HR67 HR73 HR368-HR370 HR381 HR411 HR413 HR422 HR423 HR425 MR5401-MR5403 OR144 PR8 PR43 PR50 PR70 PR95 PR108 PR112 PR114 PR118 PR1016 PR6301 PR6801 PR6802 PR7001 PR7002 PR7301 PR7702 PR8401 PR8403 PR8404 PR8406 PR8410 PR89009 PR89051 PR93029 PR93064 PR93065 PR93155 PR93157 PR93160 PR93161 PR93170 R3-R6 R206 R3106 R3107 R3111-R3124 R3129-R3131 R3139 R4007 R4008 R4011 R7219 R60761 R69693 R70296 R70298 R93098 R93102 R99531 SR19 SR30 SR262 SR271 SR274 SR275 SR286 SR7787 SR7812 SR7888 SR7890 SR7901 SR7905 SR7915 SR7917 SR7981 TC13-TC20 = MX_R_SHORT
AQ2 AQ3 M1Q9 MQ26-MQ28 PQ24 PQ25 PQ45 PQ6301 PQ9823 PQ93010 PQ93012 PQ93028 PQ93030 PQ93031 Q2 Q5-Q8 Q16 Q17 Q93 Q940-Q942 Q7201 Q9308 Q9309 Q9434-Q9437 Q9534 Q9535 Q9537 Q9540-Q9544 Q93037 Q93038 = NX3008NBKT
AQ17-AQ20 Q9432 = SSM6N15FU_TE85R_TSB
AR30 AR31 L16 L21 L22 L82 L117 L120 L122 L123 L129 L93006 PL1-PL4 PL7-PL10 PL90010-PL90013 PL93004 = BEAD
C178 C4024 D4CE1 D4CE2 PCE2-PCE7 PCE9 PCE31 PCE125 PCE690 PCE97027 PCE97028 PCE97030-PCE97035 PCE97037 PCE97038 SC53 UBC1 = CAP
CB4132 HC6 HC7 HC30 HC31 MC5401 MC5402 SC26 SC27 = C: room: AUD
CM3101-CM3104 L8 = Common_Choke_12_43
CM3301 CM3302 CM3601 CM3602 CM3605 CM3606 CM4004 CM4005 = COMMON_CHOKE_21_34_PANASONIC
CM3303 CM3603 CM3604 CM3703 CM3704 CM4003 = COMMON_CHOKE_41_32
CR1 CR2 CR4-CR7 CR22 CR23 = LED
CR15 = LED_2P_1H_PAR
D3 D522 D525 D4309 FD1 PD4 PD8 = Dual_Diode_3cathode
D4T1-D4T4 HT1-HT18 HT20 HT22 HT26-HT34 HT37-HT83 LT9 LT11 LT12 PT156-PT163 PT264 ST1 ST3 ST16 ST17 ST20 ST24-ST26 ST31-ST34 TP2601 TP2602 TP7201 = MX_TP
D519 D3103-D3106 D4301-D4308 D4310 D5501-D5503 D6301 = VPORT_0603
D521 = Dual_Diode_Convert_1anode
D524 VD11 = BAT54AW
D3101 D3102 = AZ3133_08F_R7G
D3301 D3601 D3603 D4003 M1U3 M1U4 = IP4281CZ10
D3302 D3602 D3702 = CM1213_04SO
DIMM1 DIMM2 = DDR4_260P_4HD_FOX
E16 = HEADER_2X5P_K4_PLASTRON
E61 = BTOB_CON_16P_FOXC
F1 M1F2 = POLY_FUSE
H1-H8 H11 = SCREWHOLE_87
H9 = SCREWHOLE_2NPTH_8VIA
H10 = SCREWHOLE_2NPTH_7VIA
H12 H15 H16 = HOLE_NPTH
H13 H14 = SCREWHOLE_SMT
HEATSINK = HEATSINK_2ANCHOR
HQ1 HQ2 PQ101 PQ102 Q4001 Q9344-Q9346 Q9438 Q93035 Q93036 SSD_Q2 = NPN_SOT23
J1 = DC_PWR_JACK_9P_2HOLD_FOX
J8 = LAN_12P_2HOLD_JACK_ALL_STD
J12 = USB_CON_2X9P_4HOLD_TCONN
J13 = USB_CON_2X4P_4HOLD_FOX
J68 = BTOB_CON_24P_2HOLD_MAT
J69 = WTOB_CON_30P_6HOLD_HONDA
J89 = PHONE_JACK_6P_2HOLD
J125 = HDMI_CON_19P_5HOLD_LOT_STD
J133 J200 = USB_CON_9P_2HOLD
J218 = MX_MINI_PCI_67P_4HD_LOTE
J219 = MINI_PCI_67P_4H_LOTES
J301 = PHONE_JACK_6P_4H_SINGATRN
J302 = DISPLAY_CON_20P_4HOLD
J303 = HEADER_2X4P
JMP1 = HEADER_2X3P
JP1 PJP1-PJP4 PJP6-PJP9 PJP6801 PJP89001-PJP89004 PJP90001-PJP90004 PJP93001-PJP93006 = MX_SHORT_PIN_SC
JP2801 JP2802 = ANCHOR
L4000 PL11-PL14 PL90001 PL90002 PL93001 PL93002 PL93006 PL93010 = INDUCTOR
LU3 = TRANSFORMER_LFE9110_R_0
M1Q7 M1Q8 = N_MOS_SOT23_ANPEC
O2Q2-O2Q5 = HN1C01FU
P6 P70 = WAFER_HD_1X4P_1HD_L_STD
P12 = FPC_CON_12P_4HOLD
P110 = SATA_CON_22P_6HOLD_LOTES
P305 = DE_SWITCH_4P_2HOLD_ALPS
P466 = HEADER_2X7P
PD1 = SCHOTTKY_DIODE
PPID1 = Ant_pad_rd9
PQ1 = SI7411DN
PQ5 = SI7840DP
PQ7 PQ8 PQ23 PQ93040 = SIZ300DT_T1_GE3
PQ21 Q93034 = SIA414DJ
PQ22 Q93033 = RN47A4
PQ90001 PQ93008 PQ93018 = FDPC5018SG_10V
PQ93001 PQ93002 = MX_FDMS3602_8V
PRT89001-PRT89004 = THERMISTOR
PU3 = RT8204LGQW_3
PU4 = MX_RT6575BGQW_1
PU5 = TX_AOZ2263QI_10
PU6 PU7601 = GS7105SO_1
PU7 PU76 = AP2127K_ADJTRG1
PU9 = MX_RT8231BGQW_4V
PU10 PU8401 PU8402 = APL3523AQB_ITRG
PU30 = INA213AIDCKR
